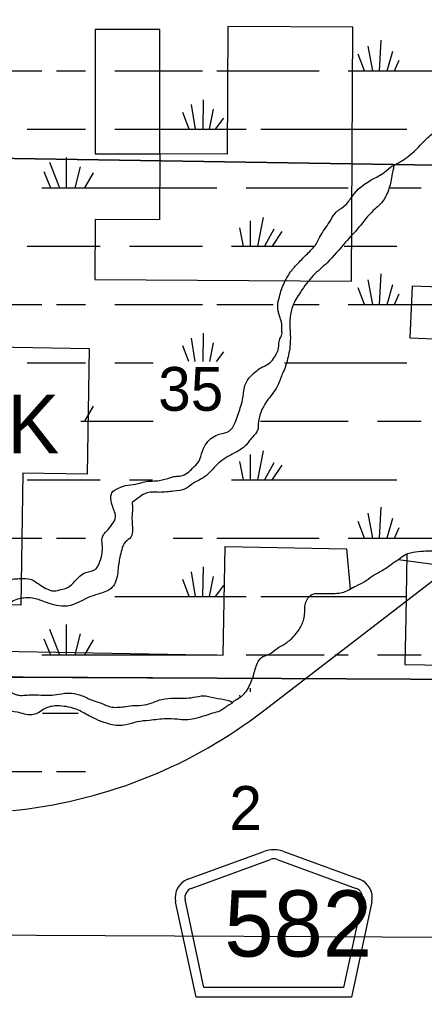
# Model space of a CAD drawing. Extents: x 380424 to 701066, y 1117407 to 1412949.
# Drawn here: x 564503 to 568664, y 1359908 to 1369965 of the extents above; entities that cross this region are included whole.
import ezdxf

# ---------------------------------------------------------------- set-up
doc = ezdxf.new("R2010")
doc.units = 0
for name, color, linetype in [('Bridges and Drawbridges US Highways', 7, 'Continuous'), ('County Routes Highway Center Lines', 7, 'Continuous'), ('Narrow River Creek and Branch and Slough', 7, 'Continuous'), ('Roadshields County Roads', 7, 'Continuous'), ('Section Lines', 7, 'Continuous'), ('Section Numbers', 7, 'Continuous'), ('State Park', 7, 'Continuous'), ('State Park Text', 7, 'Continuous'), ('Swamps', 7, 'Continuous'), ('Township  and Range lines', 7, 'Continuous'), ('US Routes Highway Center Lines', 7, 'Continuous'), ('Wide Rivers and Canals', 7, 'Continuous')]:
    doc.layers.add(name, color=color, linetype=linetype)

msp = doc.modelspace()

# ---------------------------------------------------------------- linework, layer by layer
at = {"layer": 'Bridges and Drawbridges US Highways'}
msp.add_line((568755, 1364366), (568396, 1364413), dxfattribs=at)
at = {"layer": 'County Routes Highway Center Lines'}
msp.add_lwpolyline([(615293, 1360616), (611716, 1360560), (602031, 1360504), (598282, 1360421), (586235, 1360504), (581878, 1360490), (572497, 1360518), (561822, 1360569)], dxfattribs=at)
at = {"layer": 'Narrow River Creek and Branch and Slough'}
for points in [[(568345, 1368464), (568501, 1368561), (568659, 1368714), (568770, 1368809), (568939, 1368893), (569060, 1369020), (569134, 1369094), (569218, 1369247), (569282, 1369321), (569329, 1369437), (569350, 1369574), (569345, 1369616), (569319, 1369690), (569266, 1369769), (569229, 1369859), (569203, 1369880), (569113, 1369912), (569086, 1370038), (569134, 1370149), (569134, 1370271), (569071, 1370419), (569055, 1370519), (569039, 1370587), (569034, 1370682), (569050, 1370762), (569060, 1370825), (569018, 1370915), (568923, 1370967), (568865, 1371057), (568828, 1371189), (568823, 1371353), (568659, 1372218), (568548, 1372598), (568464, 1373000), (568395, 1373227), (568348, 1373411), (568326, 1373533), (568311, 1373659), (568332, 1373881), (568348, 1373960), (568437, 1374108), (568538, 1374245), (568633, 1374404), (568728, 1374567), (568817, 1374726), (568833, 1374773), (568860, 1374831), (568897, 1374873), (569029, 1374947), (569176, 1374989), (569329, 1375000), (569493, 1375021), (569678, 1375069), (569794, 1375121), (569905, 1375164), (569984, 1375227), (570116, 1375338), (570221, 1375454), (570264, 1375480), (570301, 1375523), (570322, 1375596), (570332, 1375665), (570301, 1375797), (570274, 1375950), (570243, 1376119), (570211, 1376256), (570148, 1376430), (570090, 1376562), (569752, 1377296), (569725, 1377375), (569683, 1377476), (569657, 1377571), (569667, 1377692), (569699, 1377792), (569778, 1377919), (569831, 1378024), (569900, 1378125), (569926, 1378188), (569973, 1378294), (570005, 1378420), (570028, 1378481), (570045, 1378626), (570053, 1378767), (570136, 1378792), (570364, 1378958), (570497, 1378966), (570555, 1379090), (570596, 1379281), (570671, 1379314), (570783, 1379347), (570907, 1379364), (570874, 1379667), (570879, 1379811), (570890, 1379907), (570900, 1380036), (570973, 1380134), (571086, 1380255)], [(566683, 1362939), (566695, 1362953), (566727, 1362976), (566822, 1363050), (566864, 1363119), (566906, 1363224), (566949, 1363356), (566986, 1363409), (567070, 1363446), (567149, 1363504), (567228, 1363551), (567313, 1363620), (567376, 1363699), (567424, 1363805), (567434, 1363873), (567445, 1363979), (567476, 1364032), (567519, 1364063), (567598, 1364069), (567730, 1364069), (567867, 1364095), (567941, 1364137), (567978, 1364153), (568147, 1364259), (568258, 1364322), (568326, 1364370), (568400, 1364422), (568469, 1364470), (568574, 1364496), (568680, 1364507), (568743, 1364507), (568791, 1364502), (569286, 1364396)]]:
    msp.add_spline(points, degree=3, dxfattribs=at)
at = {"layer": 'Roadshields County Roads'}
for p, q in [((566233, 1361132), (567013, 1361418)), ((567219, 1361418), (567997, 1361132)), ((566268, 1361038), (567082, 1361337)), ((567150, 1361337), (567963, 1361038)), ((566317, 1359920), (566107, 1360902)), ((566398, 1360020), (566204, 1360923)), ((568026, 1360923), (567833, 1360020)), ((568124, 1360902), (567913, 1359920)), ((567833, 1360020), (566398, 1360020)), ((567913, 1359920), (566317, 1359920))]:
    msp.add_line(p, q, dxfattribs=at)
for centre, radius, start, end in [((567116, 1361136), 300, 69.8259, 110.1719), ((567116, 1361243), 100, 69.8259, 110.1719), ((566302, 1360944), 200, 110.1719, 192.0988), ((567928, 1360944), 200, 347.899, 69.8259), ((566302, 1360944), 100, 110.1719, 192.0988), ((567928, 1360944), 100, 347.899, 69.8259)]:
    msp.add_arc(centre, radius, start, end, dxfattribs=at)
at = {"layer": 'Section Lines'}
for points in [[(569117, 1373770), (569213, 1368463), (563794, 1368547), (563770, 1373875)], [(569213, 1368463), (569189, 1363186), (563873, 1363212), (563866, 1363212), (563794, 1368547)], [(569189, 1363186), (569160, 1357955), (569160, 1357945), (563826, 1357861), (563826, 1357878), (563865, 1363205), (563866, 1363212), (563873, 1363212)]]:
    msp.add_lwpolyline(points, close=True, dxfattribs=at)
at = {"layer": 'State Park'}
msp.add_lwpolyline([(565945, 1369864), (565280, 1369864), (565280, 1368587), (565945, 1368587), (565941, 1367908), (565279, 1367912), (565276, 1367294), (567915, 1367278), (567930, 1369886), (566645, 1369893), (566637, 1368583), (565945, 1368587)], close=True, dxfattribs=at)
for points in [[(569174, 1366666), (568519, 1366692), (568541, 1367231), (569196, 1367205)], [(563861, 1366611), (565219, 1366587), (565197, 1365293), (564538, 1365304), (564515, 1363948), (563881, 1363959)], [(564302, 1363476), (566597, 1363436), (566617, 1364551), (567864, 1364529), (567900, 1364113)], [(568483, 1364477), (568472, 1363825), (568463, 1363339), (569287, 1363325)]]:
    msp.add_lwpolyline(points, dxfattribs=at)
msp.add_spline([(567900, 1364113), (567941, 1364137), (567978, 1364153), (568147, 1364259), (568258, 1364322), (568326, 1364370), (568400, 1364422), (568469, 1364470), (568483, 1364477)], degree=3, dxfattribs=at)
at = {"layer": 'Swamps'}
for p, q in [((568204, 1369438), (568221, 1369754)), ((568133, 1369438), (568087, 1369693)), ((568281, 1369438), (568339, 1369642)), ((568048, 1369438), (567982, 1369610)), ((568357, 1369438), (568406, 1369547)), ((563682, 1369438), (564732, 1369438)), ((564882, 1369438), (565182, 1369438)), ((565482, 1369438), (566082, 1369438)), ((566082, 1369438), (566382, 1369438)), ((566532, 1369438), (567582, 1369438)), ((567882, 1369438), (568932, 1369438)), ((566389, 1368838), (566394, 1369142)), ((566310, 1368838), (566271, 1369092)), ((566456, 1368838), (566498, 1369044)), ((566248, 1368839), (566182, 1369012)), ((566518, 1368838), (566602, 1368951)), ((564582, 1368838), (565182, 1368838)), ((565482, 1368838), (566082, 1368838)), ((566082, 1368838), (566832, 1368838)), ((566982, 1368838), (568482, 1368838)), ((564981, 1368549), (564981, 1368238)), ((564812, 1368501), (564915, 1368238)), ((565126, 1368453), (565072, 1368238)), ((564751, 1368404), (564822, 1368238)), ((565259, 1368392), (565169, 1368238)), ((564732, 1368238), (566082, 1368238)), ((566082, 1368238), (566532, 1368238)), ((566832, 1368238), (567882, 1368238)), ((568312, 1368238), (568632, 1368238)), ((567006, 1367933), (566947, 1367638)), ((566765, 1367824), (566802, 1367638)), ((566873, 1367897), (566873, 1367638)), ((567115, 1367812), (567021, 1367638)), ((567199, 1367788), (567100, 1367639)), ((564582, 1367638), (565332, 1367638)), ((565632, 1367638), (566082, 1367638)), ((566082, 1367638), (566382, 1367638)), ((566682, 1367638), (567525, 1367638)), ((567841, 1367638), (568382, 1367638)), ((568204, 1367038), (568221, 1367354)), ((568048, 1367038), (567982, 1367210)), ((568133, 1367038), (568087, 1367293)), ((568281, 1367038), (568339, 1367242)), ((568357, 1367038), (568406, 1367147)), ((564882, 1367038), (565182, 1367038)), ((565482, 1367038), (566082, 1367038)), ((566082, 1367038), (566382, 1367038)), ((566532, 1367038), (567110, 1367038)), ((567314, 1367038), (567582, 1367038)), ((567882, 1367038), (568932, 1367038)), ((566389, 1366451), (566394, 1366742)), ((566244, 1366451), (566182, 1366612)), ((566308, 1366451), (566271, 1366692)), ((566458, 1366451), (566498, 1366644)), ((566527, 1366451), (566602, 1366551)), ((564582, 1366438), (565182, 1366438)), ((565482, 1366438), (565877, 1366438)), ((567227, 1366438), (568482, 1366438)), ((565259, 1365992), (565169, 1365838)), ((565132, 1365838), (565877, 1365838)), ((566980, 1365838), (567882, 1365838)), ((568182, 1365838), (568632, 1365838)), ((566873, 1365497), (566873, 1365238)), ((567006, 1365533), (566947, 1365238)), ((566764, 1365424), (566802, 1365238)), ((567115, 1365412), (567021, 1365238)), ((567199, 1365388), (567100, 1365239)), ((564582, 1365238), (565332, 1365238)), ((565632, 1365238), (565871, 1365238)), ((566682, 1365238), (568382, 1365238)), ((568133, 1364638), (568087, 1364893)), ((568204, 1364638), (568221, 1364954)), ((568048, 1364638), (567982, 1364810)), ((568280, 1364639), (568339, 1364842)), ((568357, 1364638), (568406, 1364747)), ((563682, 1364638), (564732, 1364638)), ((564882, 1364638), (565182, 1364638)), ((566082, 1364638), (566382, 1364638)), ((566532, 1364638), (567582, 1364638)), ((567882, 1364638), (568932, 1364638)), ((566310, 1364038), (566271, 1364292)), ((566388, 1364038), (566394, 1364342)), ((566248, 1364039), (566182, 1364212)), ((566456, 1364038), (566498, 1364244)), ((566518, 1364038), (566601, 1364152)), ((565482, 1364038), (566082, 1364038)), ((566082, 1364038), (566832, 1364038)), ((566982, 1364038), (568482, 1364038)), ((564812, 1363701), (564915, 1363438)), ((564981, 1363749), (564981, 1363438)), ((564751, 1363604), (564822, 1363438)), ((565126, 1363653), (565072, 1363438)), ((565259, 1363592), (565169, 1363438)), ((564732, 1363438), (566082, 1363438)), ((566082, 1363438), (566532, 1363438)), ((568182, 1363438), (568632, 1363438)), ((564740, 1362838), (565107, 1362838)), ((563682, 1362238), (564732, 1362238)), ((564882, 1362238), (565182, 1362238))]:
    msp.add_line(p, q, dxfattribs=at)
for points in [[(563685, 1367038), (564732, 1367038)], [(566832, 1363438), (567635, 1363438)], [(567742, 1363438), (567882, 1363438)], [(566873, 1363097), (566873, 1363058)], [(566764, 1363024), (566770, 1362998)]]:
    msp.add_lwpolyline(points, dxfattribs=at)
at = {"layer": 'Township  and Range lines'}
msp.add_line((563873, 1363212), (569189, 1363186), dxfattribs=at)
at = {"layer": 'US Routes Highway Center Lines'}
for p, q in [((567011, 1362864), (572331, 1366955)), ((564431, 1361838), (564503, 1361847))]:
    msp.add_line(p, q, dxfattribs=at)
msp.add_arc((563923, 1366879), 5066, 276.5815, 307.5617, dxfattribs=at)
at = {"layer": 'Wide Rivers and Canals'}
for points in [[(564772, 1364121), (564857, 1364095), (564931, 1364111), (564989, 1364126), (565036, 1364158), (565184, 1364285), (565290, 1364322), (565316, 1364364), (565353, 1364501), (565353, 1364570), (565358, 1364659), (565400, 1364712), (565453, 1364776), (565490, 1364855), (565474, 1364923), (565458, 1364971), (565453, 1365103), (565527, 1365155), (565590, 1365177), (565696, 1365192), (565801, 1365219), (565939, 1365229), (566055, 1365261), (566102, 1365272), (566160, 1365277), (566229, 1365309), (566282, 1365356), (566345, 1365425), (566382, 1365530), (566487, 1365673), (566556, 1365704), (566662, 1365741), (566725, 1365841), (566778, 1365995), (566799, 1366079), (566825, 1366221), (566894, 1366316), (566999, 1366396), (567052, 1366422), (567142, 1366527), (567168, 1366612), (567173, 1366670), (567200, 1366733), (567200, 1366754), (567200, 1366802), (567189, 1366876), (567173, 1366923), (567158, 1367018), (567173, 1367118), (567226, 1367266), (567300, 1367388), (567379, 1367477), (567474, 1367572), (567559, 1367673), (567601, 1367752), (567701, 1367905), (567759, 1367989), (567786, 1368010), (567865, 1368074), (567944, 1368179), (568144, 1368332), (568271, 1368411), (568345, 1368464), (568334, 1368385), (568319, 1368301), (568271, 1368158), (568245, 1368111), (568139, 1368005), (567991, 1367831), (567854, 1367678), (567664, 1367467), (567522, 1367335), (567390, 1367166), (567311, 1367024), (567284, 1366907), (567284, 1366765), (567284, 1366628), (567253, 1366459), (567232, 1366390), (567200, 1366316), (567152, 1366195), (567042, 1366042), (566957, 1365805), (566952, 1365752), (566894, 1365673), (566825, 1365588), (566735, 1365525), (566561, 1365419), (566482, 1365340), (566403, 1365266), (566292, 1365203), (566208, 1365145), (566086, 1365119), (565944, 1365108), (565796, 1365097), (565717, 1365045), (565659, 1365002)], [(565659, 1365002), (565664, 1364966), (565659, 1364871), (565659, 1364818), (565664, 1364728), (565648, 1364649), (565590, 1364596), (565559, 1364538), (565538, 1364459), (565516, 1364327), (565506, 1364243), (565474, 1364158), (565443, 1364121), (565311, 1364063), (565210, 1364026), (564962, 1363937), (564857, 1363952), (564757, 1363984), (564635, 1364021), (564545, 1364021), (564482, 1364010), (564419, 1363979), (564382, 1363931), (564334, 1363810), (564345, 1363773), (564340, 1363704), (564319, 1363599), (564303, 1363514), (564297, 1363388), (564308, 1363282), (564313, 1363177), (564345, 1363092), (564366, 1363082), (564456, 1363034), (564493, 1363024), (564567, 1363024), (564635, 1363029), (564751, 1363024), (564815, 1363024), (564904, 1363034), (565036, 1363045), (565147, 1363018), (565253, 1362971), (565348, 1362939), (565395, 1362918), (565453, 1362902), (565596, 1362908), (565685, 1362918), (565786, 1362923), (565965, 1362981), (566092, 1362992), (566292, 1363002), (566392, 1363018), (566509, 1362997), (566683, 1362939), (566646, 1362918), (566603, 1362886), (566561, 1362860), (566487, 1362839), (566408, 1362813), (566297, 1362781), (566213, 1362770), (566123, 1362776), (566007, 1362781), (565838, 1362765), (565712, 1362749), (565596, 1362718), (565437, 1362723), (565374, 1362744), (565353, 1362749), (565316, 1362765), (565216, 1362813), (565094, 1362876), (564915, 1362913), (564867, 1362913), (564746, 1362876), (564688, 1362839), (564630, 1362823), (564477, 1362849), (564255, 1362892), (564192, 1362918), (564102, 1362934), (563954, 1362960), (563886, 1362966), (563812, 1362966), (563685, 1362955), (563590, 1362939), (563474, 1362902), (563305, 1362860), (563179, 1362844), (563089, 1362828), (562947, 1362797), (562836, 1362781), (562741, 1362786), (562662, 1362791), (562619, 1362791), (562535, 1362902)], [(557311, 1360997), (557358, 1361061), (557363, 1361061), (557369, 1361103), (557374, 1361177), (557384, 1361272), (557448, 1361367), (557553, 1361419), (557738, 1361509), (557854, 1361525), (557981, 1361525), (558181, 1361509), (558271, 1361499), (558382, 1361483), (558582, 1361462), (558762, 1361425), (558883, 1361414), (559041, 1361361), (559200, 1361372), (559332, 1361388), (559469, 1361398), (559596, 1361361), (559722, 1361293), (559796, 1361266), (559917, 1361251), (559991, 1361256), (560028, 1361277), (560134, 1361309), (560181, 1361356), (560202, 1361409), (560229, 1361483), (560260, 1361535), (560329, 1361567), (560387, 1361604), (560482, 1361636), (560545, 1361636), (560614, 1361630), (560709, 1361652), (560825, 1361694), (560894, 1361725), (560946, 1361747), (561010, 1361794), (561041, 1361878), (561057, 1361952), (561068, 1362047), (561078, 1362163), (561110, 1362343), (561105, 1362422), (561121, 1362528), (561168, 1362628), (561247, 1362744), (561295, 1362807), (561353, 1362886), (561453, 1362997), (561527, 1363066), (561585, 1363108), (561680, 1363171), (561770, 1363235), (561902, 1363298), (561997, 1363340), (562113, 1363372), (562234, 1363382), (562345, 1363372), (562419, 1363345), (562487, 1363309), (562503, 1363282), (562551, 1363219), (562593, 1363161), (562640, 1363113), (562688, 1363050), (562741, 1362992), (562804, 1362960), (562862, 1362950), (562910, 1362950), (563026, 1362987), (563078, 1362997), (563179, 1363034), (563300, 1363066), (563453, 1363108), (563585, 1363124), (563743, 1363140), (563907, 1363140), (564028, 1363145), (564081, 1363177), (564107, 1363203), (564144, 1363272), (564166, 1363356), (564166, 1363467), (564192, 1363667), (564234, 1363889), (564234, 1364068), (564308, 1364174), (564429, 1364216), (564498, 1364221), (564625, 1364211), (564704, 1364163), (564772, 1364121)]]:
    msp.add_spline(points, degree=3, dxfattribs=at)

# ---------------------------------------------------------------- texts
at = {"layer": 'Roadshields County Roads'}
msp.add_text('582', height=680, rotation=359.9989, dxfattribs=at).set_placement((566608, 1360338))
at = {"layer": 'Section Numbers'}
for s, p in [('35', (565928, 1365946)), ('2', (566660, 1361640))]:
    msp.add_text(s, height=450, dxfattribs=at).set_placement(p)
at = {"layer": 'State Park Text'}
msp.add_text('RIVER STATE PARK', height=600, rotation=0.0001, dxfattribs=at).set_placement((557242, 1365510))

doc.saveas('drawing.dxf')
